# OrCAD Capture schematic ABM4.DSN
size A
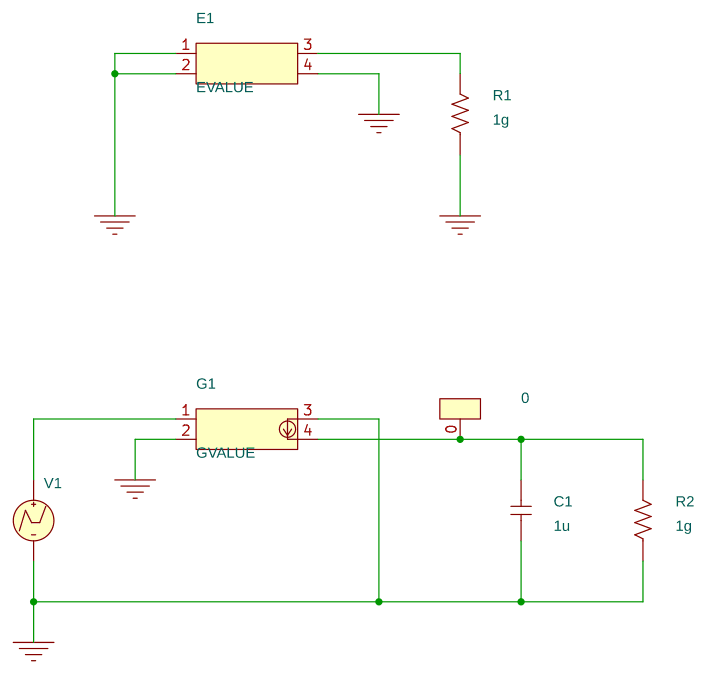
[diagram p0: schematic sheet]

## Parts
C1  1u  [RAD/CK05]
E1  EVALUE
G1  GVALUE
IC1  0
R1  1g  [AX/RC05]
R2  1g  [AX/RC05]
V1  VPWL

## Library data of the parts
C1 = C
E1 = EVALUE
G1 = GVALUE
IC1 = IC1
R1 R2 = R
V1 = VPWL

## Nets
0: C1.1 E1.1(IN+) E1.2(IN-) E1.4(OUT-) G1.2(IN-) G1.3(OUT+) R1.1 R2.1 V1.2(-)
N00251: G1.1(IN+) V1.1(+)
N00301: C1.2 G1.4(OUT-) IC1.0(+) R2.2
N00681: E1.3(OUT+) R1.2
